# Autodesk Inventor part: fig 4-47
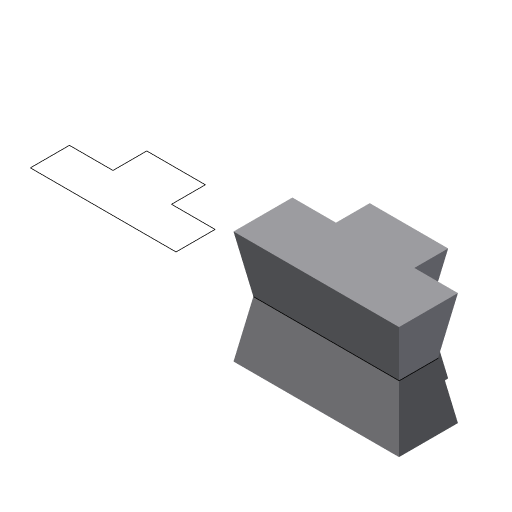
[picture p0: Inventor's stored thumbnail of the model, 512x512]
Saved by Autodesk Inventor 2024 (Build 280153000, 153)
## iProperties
Created: 2004-05
Part Number: fig 4-47
Document SubType Name: Modeling
Designer: CADCIM Technologies
Manufacturer: Standard
Standards Organization: Custom
Density: 1 g/cm^3
Material: Generic
Appearance: Default
Author: CADCIM Technologies
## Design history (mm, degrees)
sketch "Sketch1"
  geometry: L1 (31.783, 34.561)-(31.783, 22.933); L2 (31.783, 22.933)-(16.796, 22.933); L3 (16.796, 22.933)-(16.796, 9.496); L4 (16.796, 9.496)-(66.925, 9.496); L5 (66.925, 9.496)-(66.925, 22.933); L6 (66.925, 22.933)-(51.938, 22.933); L7 (51.938, 22.933)-(51.938, 34.561); L8 (51.938, 34.561)-(31.783, 34.561); L9 (-45.013, 34.561)-(-45.013, 22.933); L10 (-45.013, 22.933)-(-60, 22.933); L11 (-60, 22.933)-(-60, 9.496); L12 (-60, 9.496)-(-9.871, 9.496); L13 (-9.871, 9.496)-(-9.871, 22.933); L14 (-9.871, 22.933)-(-24.858, 22.933); L15 (-24.858, 22.933)-(-24.858, 34.561); L16 (-24.858, 34.561)-(-45.013, 34.561)
  constraints: 32 end point, 10 parallel, 4 equal length, 2 collinear, 2 perpendicular, 2 vertical
extrude "Extrusion2" new body sketch "Sketch1" stored distance "d2" = 38.75; taper "d3" = 10 deg
body "Solid2"
